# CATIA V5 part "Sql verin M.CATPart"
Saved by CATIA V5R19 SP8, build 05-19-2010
Part number: Sql verin M
Publications: "Droite.1", "Plan.1", "Droite.2", "Point.3"
Bounding box of the stored display mesh (mm): x 100 to 400, y 50 to 90, z -200 to 0
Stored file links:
  C:\Users\ThinkMotion\Desktop\EU_thinkMotion\iao\IAO_MMS_Groupe3\rdalborgo\rdalborgo\Sql verin M.CATPart
  C:\Users\ThinkMotion\Desktop\EU_thinkMotion\iao\IAO_MMS_Groupe3\rdalborgo\rdalborgo\Sql train.CATProduct
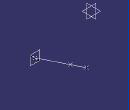
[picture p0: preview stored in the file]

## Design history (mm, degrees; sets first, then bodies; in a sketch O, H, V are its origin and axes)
External parameters (linked from other documents)
  `External.L verin` = 250.0382 mm
Set1
  Point1 "D verin": linked copy from another document
  Point2 "B verin": linked copy from another document
  Plane1: linked copy from another document
Set2
  Line1: type PtPt, FirstPoint Point1, SecondPoint Point2
  Plane2: type OffsetPt, RefPlane Plane1, RefPoint Point2
  Line2: type Normal, RefPoint Point2, RefSkin Plane1, Start -20, End 20
  Point3: type OnCurve, Support Line1, RefPoint Point2, Length -250.0382 {= -`External.L verin`}
Body1 (main body)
